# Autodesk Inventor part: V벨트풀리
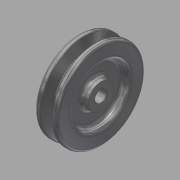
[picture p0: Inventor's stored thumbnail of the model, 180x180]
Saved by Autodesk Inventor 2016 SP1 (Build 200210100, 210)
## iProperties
Created: 2015-11
Part Number: V벨트풀리
Material: 강철, 탄소
Document SubType Name: Modeling
Designer: mduedu
Density: 1 g/cm^3
Appearance: 반광택
Author: mduedu
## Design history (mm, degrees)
sketch "스케치1"
  geometry: L1 (-9.5, 0)-(9.5, 0); L2 (0, 0)-(0, 37.7); L3 (-4.825, 37.7)-(-9.5, 37.7); L4 (-9.5, 37.7)-(-9.5, 0); L5 (0, 28.7)-(-2.074, 28.7); L6 (-2.074, 28.7)-(-4.825, 37.7); L7 (4.825, 37.7)-(9.5, 37.7); L8 (9.5, 37.7)-(9.5, 0); L9 (0, 28.7)-(2.074, 28.7); L10 (2.074, 28.7)-(4.825, 37.7); L11 (-9.5, 35)-(9.5, 35); 3 further points
  constraints: 22 end point, 7 point on line, 4 perpendicular, 3 symmetric about line, 1 coincident, 1 horizontal, 1 horizontal alignment, 1 midpoint, 1 vertical
  dimensions: "d0" = 19 distance of L1.start L1.end; "d2" = 75.4 diameter of L2.end L1 (derived); "d3" = 34 deg angle of L10 L6; "d4" = 6.3 distance between parallel lines of L11 L9; "d5" = 2.7 distance between parallel lines of L7 L11; "d6" = 8 distance of point (4, 35) point (-4, 35); "d7" = 70 diameter of L11 L1
revolve "회전1" sketch "스케치1" stored, may be unused: angle "d8" = 90 deg
sketch "스케치2"
  geometry: C1 r 24 at (0, 0); C2 r 11 at (0, 0); 1 further point
  constraints: 2 centre point, 2 coincident
  dimensions: "d9" = 48 diameter of C1; "d10" = 22 diameter of C2
extrude "돌출1" cut sketch "스케치2" distance "d11" = 6; taper "d12" = 0 deg
fillet "모깎기1" dims "d13" = 3
fillet "모깎기2" dims "d14" = 3
fillet "모깎기3" dims "d15" = 1, "d16" = 0.5, "d17" = 2
hole "구멍1" diameter "d20" = 10; stored, may be unused: countersink angle "d24" = 90 deg, drill point angle "d26" = 118 deg; dims "d18" = 10, "d19" = 10, "d21" = 6, "d22" = 4, "d23" = 2, "d25" = 8
sketch "스케치3"
  geometry: L1 (-1.5, 0)-(1.5, 0); L2 (1.5, 0)-(1.5, 6.4); L3 (1.5, 6.4)-(-1.5, 6.4); L4 (-1.5, 6.4)-(-1.5, 0); 2 further points
  constraints: 8 end point, 2 parallel, 1 coincident, 1 horizontal, 1 midpoint, 1 perpendicular
  dimensions: "d27" = 3 distance of L2.end L3.end; "d29" = 6.4 distance of L3.end L1.start
extrude "돌출2" cut sketch "스케치3" stored distance "d30" = 6; taper "d31" = 0 deg
chamfer "모따기1" distance "d32" = 0.5; stored, may be unused: second distance "d33" = 2, angle "d34" = 45 deg
node "솔리드1"
mirror "대칭1"
